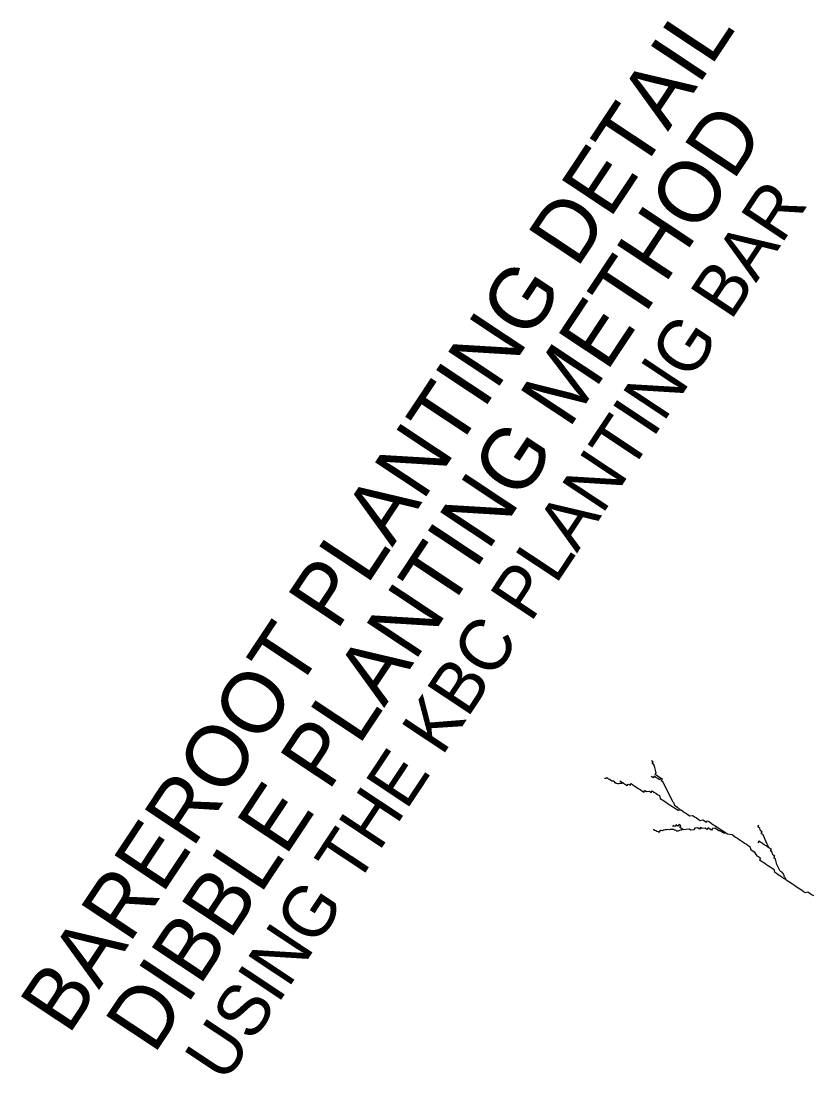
# Model space of a CAD drawing. Extents: x 561231 to 564935, y 589159 to 602519.
# Drawn here: x 564149.9 to 564238.3, y 589755.1 to 589872.7 of the extents above; entities that cross this region are included whole.
import ezdxf

# ---------------------------------------------------------------- set-up
doc = ezdxf.new("R2010")
doc.units = 0
doc.layers.add('Old_Level_1', color=7, linetype='Continuous')

msp = doc.modelspace()

# ---------------------------------------------------------------- linework, layer by layer
at = {"layer": 'Old_Level_1'}
for points in [[(564221.59, 589787.98), (564220.99, 589788.38), (564220.79, 589788.51), (564220.9, 589788.69), (564220.82, 589789), (564220.74, 589789.31), (564220.65, 589789.62), (564220.45, 589789.75), (564220.57, 589789.93), (564220.37, 589790.06)], [(564217.25, 589787.54), (564217.07, 589787.53), (564216.99, 589787.52), (564216.91, 589787.51), (564216.78, 589787.53), (564216.67, 589787.48), (564216.59, 589787.47), (564216.49, 589787.53), (564216.41, 589787.52), (564216.31, 589787.59), (564216.24, 589787.7), (564216.14, 589787.77), (564216.06, 589787.76), (564215.93, 589787.78), (564215.78, 589787.88), (564215.68, 589787.95), (564215.58, 589788.01), (564215.48, 589788.08), (564215.38, 589788.15), (564215.27, 589788.09), (564215.19, 589788.08), (564215.11, 589788.07)], [(564216.85, 589787.81), (564217.25, 589787.54), (564217.45, 589787.41), (564217.65, 589787.28), (564217.77, 589787.45), (564217.97, 589787.32), (564218.09, 589787.5), (564218.29, 589787.36), (564218.49, 589787.23), (564218.69, 589787.1), (564218.89, 589786.96), (564219.09, 589786.83), (564219.3, 589786.7), (564219.5, 589786.56), (564219.61, 589786.74), (564219.82, 589786.61), (564220.13, 589786.65), (564220.33, 589786.52), (564220.45, 589786.69), (564220.65, 589786.56), (564220.85, 589786.43), (564221.06, 589786.29), (564221.26, 589786.16), (564221.34, 589785.85), (564221.54, 589785.72), (564221.74, 589785.58), (564221.94, 589785.45), (564222.14, 589785.32), (564222.35, 589785.18), (564222.55, 589785.05), (564222.75, 589784.92), (564222.95, 589784.78), (564223.15, 589784.65), (564223.35, 589784.52), (564223.67, 589784.56), (564223.87, 589784.42), (564224.07, 589784.29), (564224.27, 589784.16), (564224.47, 589784.02), (564224.67, 589783.89), (564224.99, 589783.94), (564225.19, 589783.8), (564225.4, 589783.67), (564225.6, 589783.53), (564225.8, 589783.4), (564226.12, 589783.44), (564226.52, 589783.18), (564226.64, 589783.35), (564226.84, 589783.22), (564227.04, 589783.09), (564227.24, 589782.95), (564227.44, 589782.82), (564227.84, 589782.55), (564228.24, 589782.29), (564228.85, 589781.89), (564229.37, 589781.8), (564229.57, 589781.66), (564229.77, 589781.53), (564229.97, 589781.4), (564230.17, 589781.26), (564230.37, 589781.13), (564230.57, 589781), (564230.77, 589780.86), (564230.98, 589780.73), (564231.18, 589780.6), (564231.38, 589780.46), (564231.46, 589780.15), (564231.86, 589779.89), (564232.15, 589779.44), (564232.35, 589779.31), (564232.55, 589779.18), (564232.43, 589779), (564232.63, 589778.86), (564232.84, 589778.73), (564233.04, 589778.6), (564233.24, 589778.46), (564233.44, 589778.33), (564233.64, 589778.2), (564233.84, 589778.06), (564234.04, 589777.93), (564234.13, 589777.62), (564234.33, 589777.49), (564234.53, 589777.35), (564234.73, 589777.22), (564234.93, 589777.09), (564235.13, 589776.95), (564235.33, 589776.82), (564235.53, 589776.69), (564235.73, 589776.55), (564236.14, 589776.29), (564236.34, 589776.15), (564236.54, 589776.02), (564236.94, 589775.75), (564237.14, 589775.62), (564237.34, 589775.49), (564237.54, 589775.35), (564237.86, 589775.4), (564238.06, 589775.26), (564238.27, 589775.13), (564238.47, 589775)], [(564222.78, 589785.4), (564221.68, 589787.66), (564221.47, 589787.8), (564221.59, 589787.98), (564221.39, 589788.11), (564221.27, 589787.93), (564221.07, 589788.07), (564220.87, 589788.2), (564220.67, 589788.33), (564220.55, 589788.16), (564220.35, 589788.29)], [(564222.78, 589785.4), (564222.85, 589785.36), (564222.87, 589785.28), (564222.89, 589785.2), (564222.96, 589785.09), (564223.06, 589785.02), (564223.16, 589784.96), (564223.24, 589784.84), (564223.34, 589784.78), (564223.44, 589784.71), (564223.54, 589784.64), (564223.56, 589784.57), (564223.66, 589784.5)], [(564227.52, 589782.51), (564227.2, 589782.47), (564227.09, 589782.29), (564226.89, 589782.42), (564226.69, 589782.56), (564226.57, 589782.38), (564226.37, 589782.51), (564226.05, 589782.47), (564225.85, 589782.6), (564225.73, 589782.43), (564225.53, 589782.56), (564225.21, 589782.52), (564225.09, 589782.34), (564224.77, 589782.3), (564224.57, 589782.43), (564224.26, 589782.39), (564223.94, 589782.34), (564223.74, 589782.48), (564223.53, 589782.61), (564223.65, 589782.79), (564223.45, 589782.92), (564223.33, 589782.74), (564223.13, 589782.88), (564223.01, 589782.7), (564222.81, 589782.83), (564222.7, 589782.66)], [(564233.29, 589780.72), (564232.84, 589781.79), (564232.64, 589781.92), (564232.75, 589782.1), (564232.55, 589782.23), (564232.47, 589782.54), (564232.27, 589782.68), (564232.38, 589782.85)], [(564223.94, 589782.34), (564223.89, 589782.43), (564223.67, 589782.32), (564223.6, 589782.31), (564223.49, 589782.26), (564223.41, 589782.24), (564223.3, 589782.19), (564223.22, 589782.18), (564223.12, 589782.25), (564223.02, 589782.31), (564222.94, 589782.3), (564222.84, 589782.37), (564222.76, 589782.36), (564222.63, 589782.38), (564222.55, 589782.37), (564222.47, 589782.36), (564222.39, 589782.35), (564222.26, 589782.37), (564222.1, 589782.35), (564221.94, 589782.33), (564221.78, 589782.3), (564221.7, 589782.29), (564221.59, 589782.24), (564221.46, 589782.26), (564221.38, 589782.25), (564221.3, 589782.24), (564221.22, 589782.11), (564221.24, 589782.03), (564221.14, 589782.1), (564220.96, 589782.15), (564220.86, 589782.22), (564220.76, 589782.28), (564220.65, 589782.35), (564220.57, 589782.34)], [(564227.52, 589782.51), (564227.79, 589782.33), (564227.89, 589782.26), (564227.97, 589782.27), (564228.07, 589782.21), (564228.18, 589782.14), (564228.28, 589782.07), (564228.35, 589782.09), (564228.46, 589782.02), (564228.56, 589781.95)], [(564234.76, 589777.71), (564234.39, 589778.46), (564234.31, 589778.77), (564234.23, 589779.08), (564234.03, 589779.22), (564234.14, 589779.39), (564233.94, 589779.53), (564233.86, 589779.84), (564233.66, 589779.97), (564233.77, 589780.15), (564233.57, 589780.28), (564233.37, 589780.41), (564233.17, 589780.55), (564232.97, 589780.68), (564232.77, 589780.81), (564232.57, 589780.95), (564232.37, 589781.08), (564232.25, 589780.9)], [(564233.29, 589780.72), (564233.34, 589780.63), (564233.36, 589780.55), (564233.46, 589780.48)], [(564234.76, 589777.71), (564234.91, 589777.67), (564234.93, 589777.59), (564235.03, 589777.53), (564235.05, 589777.45), (564235.13, 589777.34), (564235.15, 589777.26), (564235.17, 589777.18), (564235.19, 589777.11), (564235.29, 589777.04), (564235.31, 589776.96), (564235.33, 589776.88)]]:
    msp.add_lwpolyline(points, dxfattribs=at)

# ---------------------------------------------------------------- texts
for s, height, p in [('BAREROOT PLANTING DETAIL', 6.882, (564155.22, 589759.3)), ('DIBBLE PLANTING METHOD', 6.882, (564164.76, 589757.13)), ('USING THE KBC PLANTING BAR', 5.735, (564172.7, 589753.89))]:
    msp.add_text(s, height=height, rotation=56.4482, dxfattribs=at).set_placement(p)

doc.saveas('drawing.dxf')
